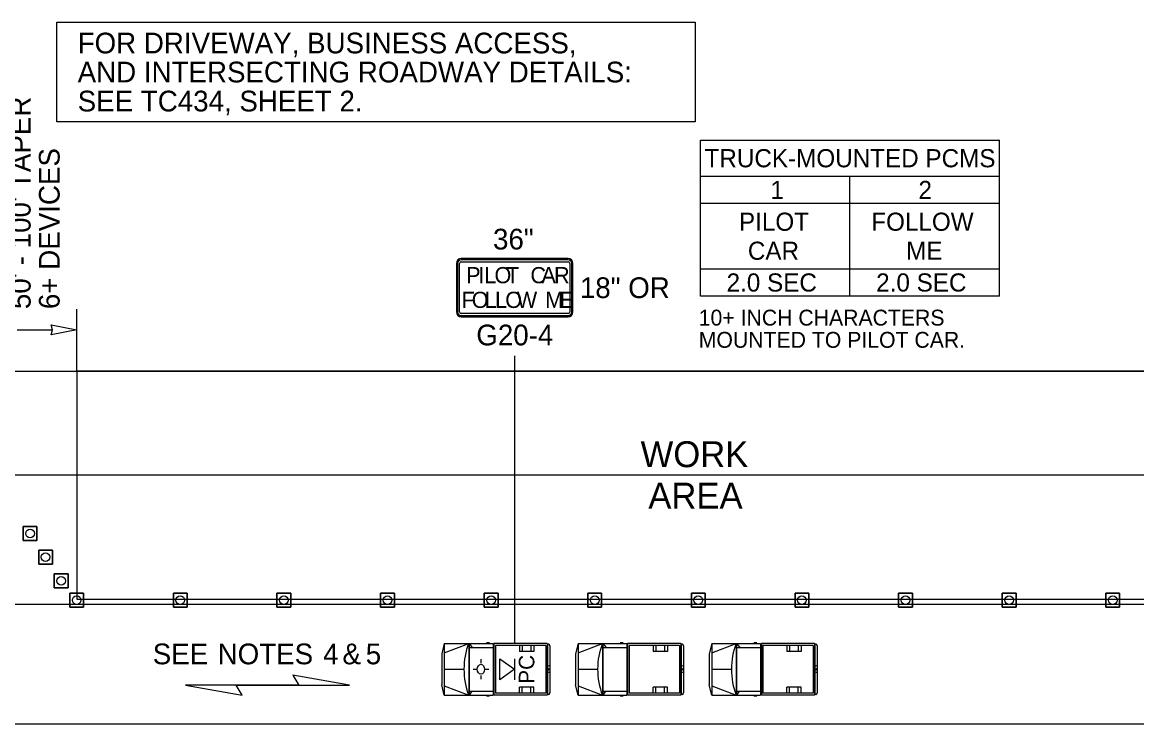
# Model space of a CAD drawing. Extents: x 99999.1 to 100095.7, y 99995 to 100010.7.
# Drawn here: x 100004.94 to 100009.243, y 100006.132 to 100008.839 of the extents above; entities that cross this region are included whole.
import ezdxf

# ---------------------------------------------------------------- set-up
doc = ezdxf.new("R2010")
doc.units = 0
for name, color, linetype in [('RD_ED_ShoulderPavedEdge', 7, 'Continuous'), ('RD_MK_LineEdgeWhite', 7, 'Continuous'), ('RD_MK_LineSkipCenter', 7, 'Continuous'), ('SH_TI_Tables', 7, 'Continuous'), ('TR_SN_ConstructionSigns', 7, 'Continuous'), ('TR_WZ_MotoristVehicle', 7, 'Continuous'), ('TR_WZ_PortableChangeMessageSign', 7, 'Continuous'), ('TR_WZ_PortableSignMountBlk-Wht', 7, 'Continuous'), ('TR_WZ_TrafficCone', 7, 'Continuous'), ('TR_WZ_WorkAreaLabel', 7, 'Continuous'), ('TR_WZ_WorkZoneDetails', 7, 'Continuous'), ('TR_WZ_WorkZoneTextCurrent', 7, 'Continuous')]:
    doc.layers.add(name, color=color, linetype=linetype)

msp = doc.modelspace()

# ---------------------------------------------------------------- linework, layer by layer
at = {"layer": 'RD_ED_ShoulderPavedEdge'}
msp.add_line((100000.1076, 100007.4923), (100015.6424, 100007.4923), dxfattribs=at)
at = {"layer": 'RD_MK_LineEdgeWhite'}
for p, q in [((100000.1076, 100007.0923), (100015.6424, 100007.0923)), ((100000.1076, 100006.1323), (100015.6424, 100006.1323))]:
    msp.add_line(p, q, dxfattribs=at)
at = {"layer": 'RD_MK_LineSkipCenter'}
msp.add_lwpolyline([(100011.15, 100006.5923), (100003.4767, 100006.5923)], dxfattribs=at)
at = {"layer": 'SH_TI_Tables'}
msp.add_lwpolyline([(100005.0739, 100008.839), (100007.5374, 100008.839), (100007.5374, 100008.455), (100005.0739, 100008.455)], close=True, dxfattribs=at)
at = {"layer": 'TR_SN_ConstructionSigns'}
for p, q in [((100007.0472, 100007.9273), (100006.6347, 100007.9273)), ((100007.0472, 100007.9226), (100006.6347, 100007.9226)), ((100006.6347, 100007.9148), (100007.0472, 100007.9148)), ((100007.0472, 100007.9226), (100007.0472, 100007.9226)), ((100006.6159, 100007.9086), (100006.6159, 100007.7211)), ((100006.6206, 100007.9086), (100006.6206, 100007.9086)), ((100006.6206, 100007.9086), (100006.6206, 100007.7211)), ((100006.6284, 100007.7211), (100006.6284, 100007.9086)), ((100007.0534, 100007.9086), (100007.0534, 100007.7211)), ((100007.0612, 100007.7211), (100007.0612, 100007.9086)), ((100007.0659, 100007.7211), (100007.0659, 100007.9086)), ((100007.0472, 100007.7148), (100006.6347, 100007.7148)), ((100006.6347, 100007.707), (100006.6347, 100007.707)), ((100006.6347, 100007.707), (100007.0472, 100007.707)), ((100006.6347, 100007.7023), (100007.0472, 100007.7023)), ((100007.0612, 100007.7211), (100007.0612, 100007.7211))]:
    msp.add_line(p, q, dxfattribs=at)
for centre, radius, start, end in [((100006.6347, 100007.9086), 0.0187, 90, 180), ((100006.6347, 100007.9086), 0.0141, 90, 180), ((100006.6347, 100007.9086), 0.00625, 90, 180), ((100007.0472, 100007.9086), 0.0187, 0, 90), ((100007.0472, 100007.9086), 0.0141, 0, 90), ((100007.0472, 100007.9086), 0.00625, 0, 90), ((100006.6347, 100007.7211), 0.0187, 180, 270), ((100006.6347, 100007.7211), 0.0141, 180, 270), ((100006.6347, 100007.7211), 0.00625, 180, 270), ((100007.0472, 100007.7211), 0.0141, 270, 0), ((100007.0472, 100007.7211), 0.00625, 270, 0), ((100007.0472, 100007.7211), 0.0187, 270, 0)]:
    msp.add_arc(centre, radius, start, end, dxfattribs=at)
at = {"layer": 'TR_WZ_MotoristVehicle'}
for p, q in [((100006.5693, 100006.4423), (100006.56, 100006.402)), ((100006.5693, 100006.4423), (100006.5693, 100006.2423)), ((100006.5693, 100006.4423), (100006.7582, 100006.4423)), ((100006.5693, 100006.4057), (100006.6638, 100006.4423)), ((100006.6638, 100006.4423), (100006.6638, 100006.2423)), ((100006.6655, 100006.4423), (100006.6655, 100006.2423)), ((100006.6655, 100006.4423), (100006.6775, 100006.4268)), ((100006.6655, 100006.4268), (100006.7582, 100006.4268)), ((100006.7324, 100006.4451), (100006.7438, 100006.4451)), ((100006.7582, 100006.4423), (100006.7582, 100006.2423)), ((100006.9667, 100006.4423), (100006.761, 100006.4423)), ((100006.761, 100006.4423), (100006.761, 100006.2423)), ((100006.9608, 100006.4344), (100006.7668, 100006.4344)), ((100006.7668, 100006.4344), (100006.7668, 100006.2503)), ((100006.8595, 100006.4344), (100006.8595, 100006.4113)), ((100006.9145, 100006.4113), (100006.8595, 100006.4113)), ((100006.8695, 100006.4344), (100006.8695, 100006.4113)), ((100006.9035, 100006.4344), (100006.9035, 100006.4113)), ((100006.9145, 100006.4344), (100006.9145, 100006.4113)), ((100006.9608, 100006.4344), (100006.9608, 100006.2503)), ((100006.9667, 100006.4423), (100006.9667, 100006.2423)), ((100006.9718, 100006.439), (100006.9674, 100006.439)), ((100006.9674, 100006.439), (100006.9674, 100006.2456)), ((100006.9763, 100006.4329), (100006.9763, 100006.2517)), ((100007.0856, 100006.4423), (100007.0763, 100006.402)), ((100007.0856, 100006.4423), (100007.0856, 100006.2423)), ((100007.0856, 100006.4423), (100007.2745, 100006.4423)), ((100007.0856, 100006.4057), (100007.18, 100006.4423)), ((100007.18, 100006.4423), (100007.18, 100006.2423)), ((100007.1817, 100006.4423), (100007.1817, 100006.2423)), ((100007.1817, 100006.4423), (100007.1938, 100006.4268)), ((100007.1817, 100006.4268), (100007.2745, 100006.4268)), ((100007.2487, 100006.4451), (100007.26, 100006.4451)), ((100007.2745, 100006.4423), (100007.2745, 100006.2423)), ((100007.4829, 100006.4423), (100007.2772, 100006.4423)), ((100007.2772, 100006.4423), (100007.2772, 100006.2423)), ((100007.4771, 100006.4344), (100007.2831, 100006.4344)), ((100007.2831, 100006.4344), (100007.2831, 100006.2503)), ((100007.3758, 100006.4344), (100007.3758, 100006.4113)), ((100007.4307, 100006.4113), (100007.3758, 100006.4113)), ((100007.3857, 100006.4344), (100007.3857, 100006.4113)), ((100007.4197, 100006.4344), (100007.4197, 100006.4113)), ((100007.4307, 100006.4344), (100007.4307, 100006.4113)), ((100007.4771, 100006.4344), (100007.4771, 100006.2503)), ((100007.4829, 100006.4423), (100007.4829, 100006.2423)), ((100007.4881, 100006.439), (100007.4836, 100006.439)), ((100007.4836, 100006.439), (100007.4836, 100006.2456)), ((100007.4926, 100006.4329), (100007.4926, 100006.2517)), ((100007.6018, 100006.4423), (100007.5926, 100006.402)), ((100007.6018, 100006.4423), (100007.6018, 100006.2423)), ((100007.6018, 100006.4423), (100007.7907, 100006.4423)), ((100007.6018, 100006.4057), (100007.6963, 100006.4423)), ((100007.6963, 100006.4423), (100007.6963, 100006.2423)), ((100007.698, 100006.4423), (100007.698, 100006.2423)), ((100007.698, 100006.4423), (100007.71, 100006.4268)), ((100007.698, 100006.4268), (100007.7907, 100006.4268)), ((100007.765, 100006.4451), (100007.7763, 100006.4451)), ((100007.7907, 100006.4423), (100007.7907, 100006.2423)), ((100007.9992, 100006.4423), (100007.7935, 100006.4423)), ((100007.7935, 100006.4423), (100007.7935, 100006.2423)), ((100007.9934, 100006.4344), (100007.7993, 100006.4344)), ((100007.7993, 100006.4344), (100007.7993, 100006.2503)), ((100007.892, 100006.4344), (100007.892, 100006.4113)), ((100007.947, 100006.4113), (100007.892, 100006.4113)), ((100007.902, 100006.4344), (100007.902, 100006.4113)), ((100007.936, 100006.4344), (100007.936, 100006.4113)), ((100007.947, 100006.4344), (100007.947, 100006.4113)), ((100007.9934, 100006.4344), (100007.9934, 100006.2503)), ((100007.9992, 100006.4423), (100007.9992, 100006.2423)), ((100008.0044, 100006.439), (100007.9999, 100006.439)), ((100007.9999, 100006.439), (100007.9999, 100006.2456)), ((100008.0088, 100006.4329), (100008.0088, 100006.2517)), ((100006.56, 100006.402), (100006.56, 100006.2827)), ((100006.7108, 100006.382), (100006.7108, 100006.3658)), ((100007.0763, 100006.402), (100007.0763, 100006.2827)), ((100007.5926, 100006.402), (100007.5926, 100006.2827)), ((100006.5693, 100006.3423), (100006.6452, 100006.3423)), ((100006.6807, 100006.3425), (100006.6933, 100006.3424)), ((100006.7249, 100006.342), (100006.7249, 100006.342)), ((100006.7417, 100006.3416), (100006.7268, 100006.3419)), ((100006.9763, 100006.3564), (100006.9674, 100006.3527)), ((100006.9763, 100006.3282), (100006.9674, 100006.332)), ((100006.9739, 100006.3423), (100006.9698, 100006.3423)), ((100006.9718, 100006.3451), (100006.9718, 100006.3395)), ((100007.0856, 100006.3423), (100007.1615, 100006.3423)), ((100007.4926, 100006.3564), (100007.4836, 100006.3527)), ((100007.4926, 100006.3282), (100007.4836, 100006.332)), ((100007.4902, 100006.3423), (100007.486, 100006.3423)), ((100007.4881, 100006.3451), (100007.4881, 100006.3395)), ((100007.6018, 100006.3423), (100007.6777, 100006.3423)), ((100008.0088, 100006.3564), (100007.9999, 100006.3527)), ((100008.0088, 100006.3282), (100007.9999, 100006.332)), ((100008.0064, 100006.3423), (100008.0023, 100006.3423)), ((100008.0044, 100006.3451), (100008.0044, 100006.3395)), ((100006.5693, 100006.2423), (100006.56, 100006.2827)), ((100006.5693, 100006.279), (100006.6638, 100006.2423)), ((100006.7115, 100006.3039), (100006.7112, 100006.3189)), ((100007.0856, 100006.2423), (100007.0763, 100006.2827)), ((100007.0856, 100006.279), (100007.18, 100006.2423)), ((100007.6018, 100006.2423), (100007.5926, 100006.2827)), ((100007.6018, 100006.279), (100007.6963, 100006.2423)), ((100006.5693, 100006.2423), (100006.7582, 100006.2423)), ((100006.6655, 100006.2578), (100006.7582, 100006.2578)), ((100006.6754, 100006.2578), (100006.6655, 100006.2423)), ((100006.7324, 100006.2395), (100006.7438, 100006.2395)), ((100006.9667, 100006.2423), (100006.761, 100006.2423)), ((100006.9608, 100006.2503), (100006.7668, 100006.2503)), ((100006.8595, 100006.2503), (100006.8595, 100006.2733)), ((100006.9145, 100006.2733), (100006.8595, 100006.2733)), ((100006.8695, 100006.2503), (100006.8695, 100006.2733)), ((100006.9035, 100006.2503), (100006.9035, 100006.2733)), ((100006.9145, 100006.2503), (100006.9145, 100006.2733)), ((100006.9718, 100006.2456), (100006.9674, 100006.2456)), ((100007.0856, 100006.2423), (100007.2745, 100006.2423)), ((100007.1817, 100006.2578), (100007.2745, 100006.2578)), ((100007.1917, 100006.2578), (100007.1817, 100006.2423)), ((100007.2487, 100006.2395), (100007.26, 100006.2395)), ((100007.4829, 100006.2423), (100007.2772, 100006.2423)), ((100007.4771, 100006.2503), (100007.2831, 100006.2503)), ((100007.3758, 100006.2503), (100007.3758, 100006.2733)), ((100007.4307, 100006.2733), (100007.3758, 100006.2733)), ((100007.3857, 100006.2503), (100007.3857, 100006.2733)), ((100007.4197, 100006.2503), (100007.4197, 100006.2733)), ((100007.4307, 100006.2503), (100007.4307, 100006.2733)), ((100007.4881, 100006.2456), (100007.4836, 100006.2456)), ((100007.6018, 100006.2423), (100007.7907, 100006.2423)), ((100007.698, 100006.2578), (100007.7907, 100006.2578)), ((100007.708, 100006.2578), (100007.698, 100006.2423)), ((100007.765, 100006.2395), (100007.7763, 100006.2395)), ((100007.9992, 100006.2423), (100007.7935, 100006.2423)), ((100007.9934, 100006.2503), (100007.7993, 100006.2503)), ((100007.892, 100006.2503), (100007.892, 100006.2733)), ((100007.947, 100006.2733), (100007.892, 100006.2733)), ((100007.902, 100006.2503), (100007.902, 100006.2733)), ((100007.936, 100006.2503), (100007.936, 100006.2733)), ((100007.947, 100006.2503), (100007.947, 100006.2733)), ((100008.0044, 100006.2456), (100007.9999, 100006.2456))]:
    msp.add_line(p, q, dxfattribs=at)
for centre, major_axis, start_param, end_param in [((100006.7987, 100006.3423), (0, -0.2099), 4.215667, 5.208926), ((100006.9718, 100006.4329), (0, 0.0061), 4.712389, 6.283185), ((100007.315, 100006.3423), (0, -0.2099), 4.215667, 5.208926), ((100007.4881, 100006.4329), (0, 0.0061), 4.712389, 6.283185), ((100007.8313, 100006.3423), (0, -0.2099), 4.215667, 5.208926), ((100008.0044, 100006.4329), (0, 0.0061), 4.712389, 6.283185), ((100006.9718, 100006.2517), (0, -0.0061), 0, 1.570796), ((100007.4881, 100006.2517), (0, -0.0061), 0, 1.570796), ((100008.0044, 100006.2517), (0, -0.0061), 0, 1.570796)]:
    msp.add_ellipse(centre, major_axis=major_axis, ratio=0.73155, start_param=start_param, end_param=end_param, dxfattribs=at)
for centre, major_axis in [((100006.7108, 100006.3423), (0, 0.0193)), ((100006.9718, 100006.3423), (0, 0.00282)), ((100007.4881, 100006.3423), (0, 0.00282)), ((100008.0044, 100006.3423), (0, 0.00282))]:
    msp.add_ellipse(centre, major_axis=major_axis, ratio=0.73155, dxfattribs=at)
at = {"layer": 'TR_WZ_PortableChangeMessageSign'}
for p, q in [((100007.5582, 100008.3845), (100008.7132, 100008.3845)), ((100007.5582, 100007.7825), (100007.5582, 100008.3845)), ((100008.7132, 100007.7825), (100008.7132, 100008.3845)), ((100008.7132, 100008.2445), (100007.5582, 100008.2445)), ((100008.1357, 100007.7825), (100008.1357, 100008.2445)), ((100008.1357, 100008.1395), (100007.5582, 100008.1395)), ((100008.7132, 100008.1395), (100008.1357, 100008.1395)), ((100007.5582, 100007.8875), (100008.1357, 100007.8875)), ((100008.1357, 100007.8875), (100008.7132, 100007.8875)), ((100008.7132, 100007.7825), (100007.5582, 100007.7825))]:
    msp.add_line(p, q, dxfattribs=at)
at = {"layer": 'TR_WZ_PortableSignMountBlk-Wht'}
msp.add_line((100006.8406, 100006.3822), (100006.8406, 100006.3022), dxfattribs=at)
msp.add_lwpolyline([(100006.8406, 100006.3423), (100006.7832, 100006.3022), (100006.7832, 100006.3822)], close=True, dxfattribs=at)
at = {"layer": 'TR_WZ_TrafficCone'}
for points in [[(100004.9434, 100006.8931), (100004.9967, 100006.8931), (100004.9967, 100006.8397), (100004.9434, 100006.8397), (100004.9434, 100006.8931)], [(100004.9434, 100006.8397), (100004.9967, 100006.8397), (100004.9967, 100006.8931), (100004.9434, 100006.8931), (100004.9434, 100006.8397)], [(100005.0034, 100006.8017), (100005.0567, 100006.8017), (100005.0567, 100006.7484), (100005.0034, 100006.7484), (100005.0034, 100006.8017)], [(100005.0034, 100006.7484), (100005.0567, 100006.7484), (100005.0567, 100006.8017), (100005.0034, 100006.8017), (100005.0034, 100006.7484)], [(100005.0634, 100006.7104), (100005.1167, 100006.7104), (100005.1167, 100006.6571), (100005.0634, 100006.6571), (100005.0634, 100006.7104)], [(100005.0634, 100006.6571), (100005.1167, 100006.6571), (100005.1167, 100006.7104), (100005.0634, 100006.7104), (100005.0634, 100006.6571)], [(100005.1234, 100006.6357), (100005.1767, 100006.6357), (100005.1767, 100006.5823), (100005.1234, 100006.5823), (100005.1234, 100006.6357)], [(100005.1234, 100006.5823), (100005.1767, 100006.5823), (100005.1767, 100006.6357), (100005.1234, 100006.6357), (100005.1234, 100006.5823)], [(100005.5234, 100006.6357), (100005.5767, 100006.6357), (100005.5767, 100006.5823), (100005.5234, 100006.5823), (100005.5234, 100006.6357)], [(100005.5234, 100006.5823), (100005.5767, 100006.5823), (100005.5767, 100006.6357), (100005.5234, 100006.6357), (100005.5234, 100006.5823)], [(100005.9234, 100006.6357), (100005.9767, 100006.6357), (100005.9767, 100006.5823), (100005.9234, 100006.5823), (100005.9234, 100006.6357)], [(100005.9234, 100006.5823), (100005.9767, 100006.5823), (100005.9767, 100006.6357), (100005.9234, 100006.6357), (100005.9234, 100006.5823)], [(100006.3234, 100006.6357), (100006.3767, 100006.6357), (100006.3767, 100006.5823), (100006.3234, 100006.5823), (100006.3234, 100006.6357)], [(100006.3234, 100006.5823), (100006.3767, 100006.5823), (100006.3767, 100006.6357), (100006.3234, 100006.6357), (100006.3234, 100006.5823)], [(100006.7234, 100006.6357), (100006.7767, 100006.6357), (100006.7767, 100006.5823), (100006.7234, 100006.5823), (100006.7234, 100006.6357)], [(100006.7234, 100006.5823), (100006.7767, 100006.5823), (100006.7767, 100006.6357), (100006.7234, 100006.6357), (100006.7234, 100006.5823)], [(100007.1234, 100006.6357), (100007.1767, 100006.6357), (100007.1767, 100006.5823), (100007.1234, 100006.5823), (100007.1234, 100006.6357)], [(100007.1234, 100006.5823), (100007.1767, 100006.5823), (100007.1767, 100006.6357), (100007.1234, 100006.6357), (100007.1234, 100006.5823)], [(100007.5234, 100006.6357), (100007.5767, 100006.6357), (100007.5767, 100006.5823), (100007.5234, 100006.5823), (100007.5234, 100006.6357)], [(100007.5234, 100006.5823), (100007.5767, 100006.5823), (100007.5767, 100006.6357), (100007.5234, 100006.6357), (100007.5234, 100006.5823)], [(100007.9234, 100006.6357), (100007.9767, 100006.6357), (100007.9767, 100006.5823), (100007.9234, 100006.5823), (100007.9234, 100006.6357)], [(100007.9234, 100006.5823), (100007.9767, 100006.5823), (100007.9767, 100006.6357), (100007.9234, 100006.6357), (100007.9234, 100006.5823)], [(100008.3234, 100006.6357), (100008.3767, 100006.6357), (100008.3767, 100006.5823), (100008.3234, 100006.5823), (100008.3234, 100006.6357)], [(100008.3234, 100006.5823), (100008.3767, 100006.5823), (100008.3767, 100006.6357), (100008.3234, 100006.6357), (100008.3234, 100006.5823)], [(100008.7234, 100006.6357), (100008.7767, 100006.6357), (100008.7767, 100006.5823), (100008.7234, 100006.5823), (100008.7234, 100006.6357)], [(100008.7234, 100006.5823), (100008.7767, 100006.5823), (100008.7767, 100006.6357), (100008.7234, 100006.6357), (100008.7234, 100006.5823)], [(100009.1234, 100006.6357), (100009.1767, 100006.6357), (100009.1767, 100006.5823), (100009.1234, 100006.5823), (100009.1234, 100006.6357)], [(100009.1234, 100006.5823), (100009.1767, 100006.5823), (100009.1767, 100006.6357), (100009.1234, 100006.6357), (100009.1234, 100006.5823)]]:
    msp.add_lwpolyline(points, dxfattribs=at)
for centre in [(100004.97, 100006.8664), (100005.03, 100006.7751), (100005.09, 100006.6837), (100005.15, 100006.609), (100005.55, 100006.609), (100005.95, 100006.609), (100006.35, 100006.609), (100006.75, 100006.609), (100007.15, 100006.609), (100007.55, 100006.609), (100007.95, 100006.609), (100008.35, 100006.609), (100008.75, 100006.609), (100009.15, 100006.609)]:
    msp.add_circle(centre, 0.0167, dxfattribs=at)
at = {"layer": 'TR_WZ_WorkZoneDetails'}
for p, q in [((100005.15, 100007.4923), (100005.15, 100007.7323)), ((100004.9204, 100007.6523), (100005.0563, 100007.6523)), ((100006.8406, 100007.5523), (100006.8406, 100006.4423)), ((100005.7663, 100006.2816), (100006.0074, 100006.2816)), ((100006.0074, 100006.2816), (100005.7663, 100006.2816))]:
    msp.add_line(p, q, dxfattribs=at)
for points in [[(100005.15, 100007.6523), (100005.0517, 100007.6331), (100005.0563, 100007.6523), (100005.0517, 100007.6716)], [(100005.15, 100007.4923), (100005.15, 100006.6123), (100009.9338, 100006.6123), (100009.9338, 100007.4923)], [(100005.5698, 100006.2816), (100005.7886, 100006.243), (100005.7663, 100006.2816)], [(100006.2039, 100006.2816), (100005.9851, 100006.3202), (100006.0074, 100006.2816)]]:
    msp.add_lwpolyline(points, close=True, dxfattribs=at)

# ---------------------------------------------------------------- texts
at = {"layer": 'SH_TI_Tables'}
for s, p in [('FOR DRIVEWAY, BUSINESS ACCESS,', (100005.1539, 100008.719)), ('AND INTERSECTING ROADWAY DETAILS:', (100005.1539, 100008.607)), ('SEE TC434, SHEET 2.', (100005.1539, 100008.495))]:
    msp.add_text(s, height=0.08, rotation=360, dxfattribs=at).set_placement(p)
at = {"layer": 'TR_SN_ConstructionSigns'}
for s, p in [('36"', (100006.7575, 100007.9623)), ('18" OR', (100007.0928, 100007.7748)), ('G20-4', (100006.6929, 100007.5923))]:
    msp.add_text(s, height=0.08, rotation=360, dxfattribs=at).set_placement(p)
for s, p in [('P', (100006.6537, 100007.832)), ('I', (100006.7012, 100007.832)), ('L', (100006.7237, 100007.832)), ('O', (100006.7631, 100007.832)), ('T', (100006.8075, 100007.832)), ('C', (100006.9018, 100007.832)), ('A', (100006.9443, 100007.832)), ('R', (100006.9931, 100007.832)), ('F', (100006.6359, 100007.7367)), ('O', (100006.6753, 100007.7367)), ('L', (100006.7247, 100007.7367)), ('L', (100006.7653, 100007.7367)), ('O', (100006.8047, 100007.7367)), ('W', (100006.849, 100007.7367)), ('M', (100006.959, 100007.7367)), ('E', (100007.014, 100007.7367))]:
    msp.add_text(s, height=0.0625, dxfattribs=at).set_placement(p)
at = {"layer": 'TR_WZ_MotoristVehicle'}
msp.add_text('PC', height=0.06, rotation=90, dxfattribs=at).set_placement((100006.917, 100006.2863))
at = {"layer": 'TR_WZ_PortableChangeMessageSign'}
for s, height, p in [('TRUCK-MOUNTED PCMS', 0.07, (100007.5742, 100008.2795)), ('1', 0.07, (100007.8285, 100008.157)), ('2', 0.07, (100008.4, 100008.157)), ('PILOT', 0.07, (100007.707, 100008.0345)), ('FOLLOW', 0.07, (100008.2178, 100008.0345)), ('CAR', 0.07, (100007.7414, 100007.9225)), ('ME', 0.07, (100008.3525, 100007.9225)), ('2.0 SEC', 0.07, (100007.6593, 100007.8)), ('2.0 SEC', 0.07, (100008.2368, 100007.8)), ('10+ INCH CHARACTERS', 0.06125, (100007.5517, 100007.6687)), ('MOUNTED TO PILOT CAR.', 0.06125, (100007.5517, 100007.583))]:
    msp.add_text(s, height=height, rotation=360, dxfattribs=at).set_placement(p)
at = {"layer": 'TR_WZ_WorkAreaLabel'}
for s, p in [('WORK', (100007.3273, 100007.1223)), ('AREA', (100007.357, 100006.9623))]:
    msp.add_text(s, height=0.1, dxfattribs=at).set_placement(p)
at = {"layer": 'TR_WZ_WorkZoneTextCurrent'}
for s, p in [("50' - 100' TAPER", (100004.9723, 100007.7323)), ('6+ DEVICES', (100005.0843, 100007.7323))]:
    msp.add_text(s, height=0.08, rotation=90, dxfattribs=at).set_placement(p)
for s, p in [('SEE', (100005.4437, 100006.3616)), ('NOTES', (100005.6943, 100006.3616)), ('4', (100006.1018, 100006.3616)), ('&', (100006.1762, 100006.3616)), ('5', (100006.266, 100006.3616))]:
    msp.add_text(s, height=0.08, dxfattribs=at).set_placement(p)

doc.saveas('drawing.dxf')
